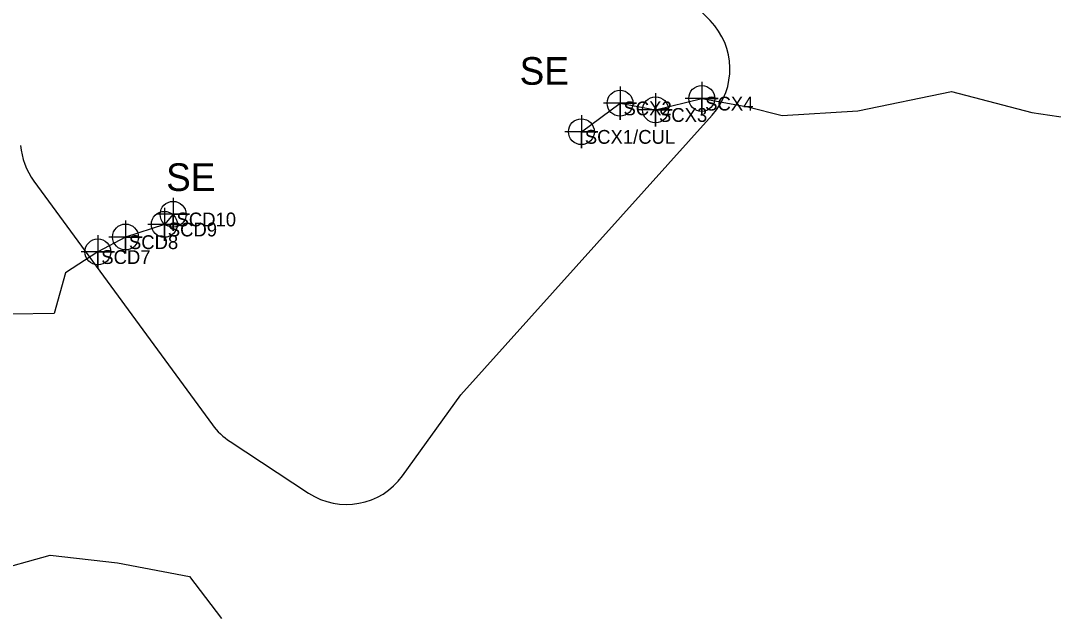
# Model space of a CAD drawing. Extents: x 1253697 to 1278588, y 912189 to 981699.
# Drawn here: x 1260665 to 1261412, y 913272 to 913705 of the extents above; entities that cross this region are included whole.
import ezdxf

# ---------------------------------------------------------------- set-up
doc = ezdxf.new("R2010")
doc.units = 0
for name, color, linetype in [('Default', 7, 'Continuous'), ('Exist Hydro Jurisdictional Stream or Body of Water Mitigable', 7, 'Continuous'), ('Exist Hydro Jurisdictional Stream or Body of Water Mitigable Cogo Comment', 7, 'Continuous'), ('Exist Hydro Jurisdictional Stream or Body of Water Mitigable Cogo Number', 7, 'Continuous'), ('Exist Hydro Jurisdictional Stream or Body of Water Mitigable Cogo Point CELL', 7, 'Continuous')]:
    doc.layers.add(name, color=color, linetype=linetype)

msp = doc.modelspace()

# ---------------------------------------------------------------- linework, layer by layer
at = {"layer": 'Default'}
for p, q in [((1260674.04, 913588.57), (1260803.29, 913412.2)), ((1260674.04, 913588.57), (1260803.29, 913412.2)), ((1260674.04, 913588.57), (1260803.29, 913412.2)), ((1260674.04, 913588.57), (1260803.29, 913412.2)), ((1260816.16, 913399.97), (1260872.91, 913362.66)), ((1260816.16, 913399.97), (1260872.91, 913362.66)), ((1260816.16, 913399.97), (1260872.91, 913362.66)), ((1260816.16, 913399.97), (1260872.91, 913362.66))]:
    msp.add_line(p, q, dxfattribs=at)
for points in [[(1261163.73, 913704.85), (1261121.23, 913748.28), (1261130.66, 913757.5)], [(1261163.73, 913704.85), (1261121.23, 913748.28), (1261130.66, 913757.5)], [(1261163.73, 913704.85), (1261121.23, 913748.28), (1261130.66, 913757.5)], [(1261163.73, 913704.85), (1261121.23, 913748.28), (1261130.66, 913757.5)], [(1260940.95, 913375.22), (1260983.12, 913433.78), (1261165.2, 913636.46)], [(1260940.95, 913375.22), (1260983.12, 913433.78), (1261165.2, 913636.46)], [(1260940.95, 913375.22), (1260983.12, 913433.78), (1261165.2, 913636.46)], [(1260940.95, 913375.22), (1260983.12, 913433.78), (1261165.2, 913636.46)]]:
    msp.add_lwpolyline(points, dxfattribs=at)
for centre, start, end in [((1261128, 913669.88), 318.06592, 44.38147), ((1261128, 913669.88), 318.06592, 44.38147), ((1261128, 913669.88), 318.06592, 44.38147), ((1261128, 913669.88), 318.06592, 44.38147), ((1260714.38, 913618.13), 184.13245, 216.23447), ((1260714.38, 913618.13), 184.13245, 216.23447), ((1260714.38, 913618.13), 184.13245, 216.23447), ((1260714.38, 913618.13), 184.13245, 216.23447), ((1260843.62, 913441.75), 216.23447, 236.67587), ((1260843.62, 913441.75), 216.23447, 236.67587), ((1260843.62, 913441.75), 216.23447, 236.67587), ((1260843.62, 913441.75), 216.23447, 236.67587), ((1260900.38, 913404.44), 236.67587, 324.2399), ((1260900.38, 913404.44), 236.67587, 324.2399), ((1260900.38, 913404.44), 236.67587, 324.2399), ((1260900.38, 913404.44), 236.67587, 324.2399)]:
    msp.add_arc(centre, 50, start, end, dxfattribs=at)
at = {"layer": 'Exist Hydro Jurisdictional Stream or Body of Water Mitigable'}
for points in [[(1261070.47, 913624.41), (1261098.45, 913645.05), (1261124.14, 913640.28), (1261157.6, 913648.52), (1261191.06, 913642.43), (1261215.9, 913636.16), (1261270.63, 913639.47), (1261338.38, 913653.56), (1261396.49, 913638.34), (1261455.14, 913629.71), (1261496.13, 913633.98)], [(1260454.11, 913565.74), (1260476.4, 913530.66), (1260475.47, 913502.82), (1260486.95, 913486.95), (1260487.32, 913472.91), (1260512.92, 913463.55), (1260540.87, 913463.39), (1260564.97, 913454.8), (1260585.56, 913454.54), (1260604.3, 913432.26), (1260607.24, 913388.44), (1260609.81, 913378.31), (1260612.63, 913372.09), (1260617.63, 913352.2), (1260642.4, 913305.64), (1260685.76, 913317.83), (1260734.55, 913312.25), (1260786.86, 913302.29), (1260809.8, 913271.97)], [(1260774.85, 913564.6), (1260768.53, 913557.32), (1260740.41, 913548.15), (1260720.39, 913537.37), (1260696.86, 913522.16), (1260688.75, 913492.8), (1260658.06, 913492.27), (1260638.65, 913459.57), (1260620.96, 913427.1), (1260604.3, 913432.26)]]:
    msp.add_lwpolyline(points, dxfattribs=at)
at = {"layer": 'Exist Hydro Jurisdictional Stream or Body of Water Mitigable Cogo Point CELL'}
for points in [[(1261157.6, 913660.52), (1261157.6, 913636.52), (1261157.6, 913648.52), (1261169.6, 913648.52), (1261145.6, 913648.52)], [(1261098.45, 913657.05), (1261098.45, 913633.05), (1261098.45, 913645.05), (1261110.45, 913645.05), (1261086.45, 913645.05)], [(1261124.14, 913652.28), (1261124.14, 913628.28), (1261124.14, 913640.28), (1261136.14, 913640.28), (1261112.14, 913640.28)], [(1261070.47, 913636.41), (1261070.47, 913612.41), (1261070.47, 913624.41), (1261082.47, 913624.41), (1261058.47, 913624.41)], [(1260774.85, 913576.6), (1260774.85, 913552.6), (1260774.85, 913564.6), (1260786.85, 913564.6), (1260762.85, 913564.6)], [(1260768.53, 913569.32), (1260768.53, 913545.32), (1260768.53, 913557.32), (1260780.53, 913557.32), (1260756.53, 913557.32)], [(1260740.41, 913560.15), (1260740.41, 913536.15), (1260740.41, 913548.15), (1260752.41, 913548.15), (1260728.41, 913548.15)], [(1260720.39, 913549.37), (1260720.39, 913525.37), (1260720.39, 913537.37), (1260732.39, 913537.37), (1260708.39, 913537.37)]]:
    msp.add_lwpolyline(points, dxfattribs=at)
for centre in [(1261098.45, 913645.05), (1261157.6, 913648.52), (1261124.14, 913640.28), (1261070.47, 913624.41), (1260774.85, 913564.6), (1260768.53, 913557.32), (1260740.41, 913548.15), (1260720.39, 913537.37)]:
    msp.add_circle(centre, 9.38, dxfattribs=at)

# ---------------------------------------------------------------- texts
at = {"layer": 'Exist Hydro Jurisdictional Stream or Body of Water Mitigable Cogo Comment'}
for s, p in [('SCX2', (1261100.95, 913636.3)), ('SCX4', (1261160.1, 913639.77)), ('SCX3', (1261126.64, 913631.53)), ('SCX1/CUL', (1261072.97, 913615.66)), ('SCD10', (1260777.35, 913555.85)), ('SCD9', (1260771.03, 913548.57)), ('SCD8', (1260742.91, 913539.4)), ('SCD7', (1260722.89, 913528.62))]:
    msp.add_text(s, height=10, dxfattribs=at).set_placement(p)
at = {"layer": 'Exist Hydro Jurisdictional Stream or Body of Water Mitigable Cogo Number'}
for p in [(1261025.76, 913658.42), (1260769.85, 913581.51)]:
    msp.add_text('SE', height=20, dxfattribs=at).set_placement(p)

doc.saveas('drawing.dxf')
